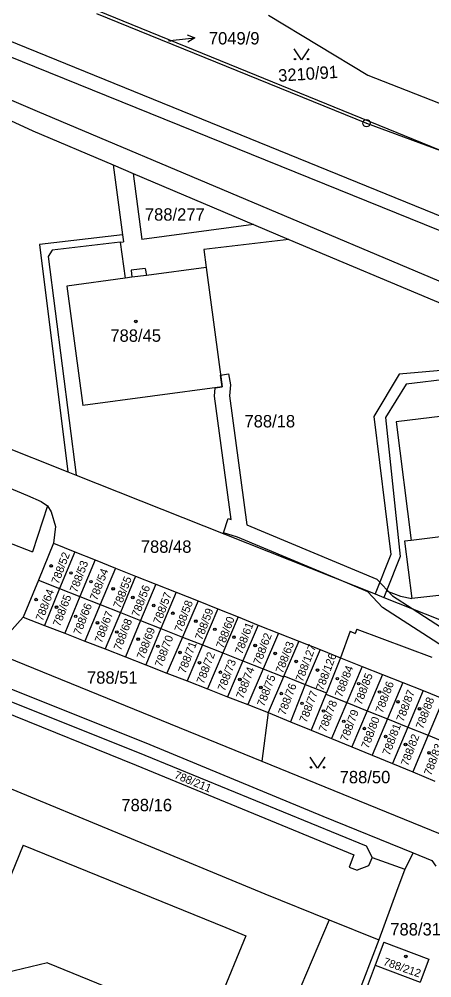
# Model space of a CAD drawing. Extents: x -593183 to -588034, y -1130415 to -1124994.
# Drawn here: x -591933.7 to -591877.1, y -1128398.9 to -1128267.2 of the extents above; entities that cross this region are included whole.
import ezdxf

# ---------------------------------------------------------------- set-up
doc = ezdxf.new("R2010")
doc.units = 0
for name, color, linetype in [('Vrstva 1', 7, 'Continuous'), ('Vrstva 16', 7, 'Continuous'), ('Vrstva 18', 7, 'Continuous'), ('Vrstva 19', 7, 'Continuous'), ('Vrstva 24', 7, 'Continuous'), ('Vrstva 25', 7, 'Continuous'), ('Vrstva 27', 7, 'Continuous'), ('Vrstva 4', 7, 'Continuous')]:
    doc.layers.add(name, color=color, linetype=linetype)

msp = doc.modelspace()

# ---------------------------------------------------------------- linework, layer by layer
at = {"layer": 'Vrstva 1'}
for p, q in [((-591960.97, -1128261.67), (-591931.65, -1128273.68)), ((-591955.86, -1128261.68), (-591814.3, -1128319.36)), ((-591875.91, -1128285.24), (-591925.43, -1128265.02)), ((-591923.14, -1128266.39), (-591886.05, -1128281.47)), ((-591899.53, -1128266.62), (-591885.86, -1128274.85)), ((-591946.82, -1128273.12), (-591931.29, -1128279.8)), ((-591931.65, -1128273.68), (-591845.27, -1128308.65)), ((-591885.86, -1128274.85), (-591849.68, -1128289.18)), ((-591947.36, -1128275.43), (-591931.88, -1128282.5)), ((-591931.29, -1128279.8), (-591692.48, -1128380.79)), ((-591886.05, -1128281.47), (-591875.91, -1128285.24)), ((-591931.88, -1128282.5), (-591920.82, -1128287.21)), ((-591920.82, -1128287.21), (-591918.08, -1128288.37)), ((-591920.82, -1128287.21), (-591919.56, -1128296.79)), ((-591918.08, -1128288.37), (-591901.57, -1128295.39)), ((-591901.57, -1128295.39), (-591896.73, -1128297.44)), ((-591919.56, -1128296.79), (-591919.43, -1128297.76)), ((-591896.73, -1128297.44), (-591908.41, -1128298.84)), ((-591896.73, -1128297.44), (-591875.33, -1128306.43)), ((-591919.87, -1128297.81), (-591919.43, -1128297.76)), ((-591919.87, -1128297.81), (-591919.2, -1128302.75)), ((-591908.41, -1128298.84), (-591908.06, -1128301.32)), ((-591916.44, -1128301.42), (-591918.36, -1128301.66)), ((-591916.44, -1128301.42), (-591916.27, -1128302.38)), ((-591908.06, -1128301.32), (-591916.27, -1128302.38)), ((-591908.06, -1128301.32), (-591905.88, -1128317.72)), ((-591918.25, -1128302.63), (-591919.2, -1128302.75)), ((-591918.36, -1128301.66), (-591918.25, -1128302.63)), ((-591919.2, -1128302.75), (-591927.21, -1128303.87)), ((-591927.21, -1128303.87), (-591925.02, -1128320.28)), ((-591905.88, -1128317.72), (-591925.02, -1128320.28)), ((-591873.96, -1128321.52), (-591881.99, -1128322.5)), ((-591881.99, -1128322.5), (-591879.92, -1128338.81)), ((-591938.97, -1128324.65), (-591927.04, -1128329.4)), ((-591927.04, -1128329.4), (-591925.93, -1128329.84)), ((-591925.93, -1128329.84), (-591884.86, -1128346.18)), ((-591935.41, -1128331.44), (-591932.59, -1128332.65)), ((-591932.59, -1128332.65), (-591930.7, -1128333.45)), ((-591930.7, -1128333.45), (-591929.87, -1128334.08)), ((-591929.87, -1128334.08), (-591929.34, -1128334.9)), ((-591929.34, -1128334.9), (-591928.74, -1128336.89)), ((-591928.74, -1128336.89), (-591929.02, -1128339.21)), ((-591866.81, -1128337.15), (-591879.92, -1128338.81)), ((-591929.02, -1128339.21), (-591931.1, -1128344.28)), ((-591929.02, -1128339.21), (-591926.1, -1128340.38)), ((-591926.1, -1128340.38), (-591928.18, -1128345.43)), ((-591926.1, -1128340.38), (-591923.31, -1128341.49)), ((-591923.31, -1128341.49), (-591925.4, -1128346.53)), ((-591923.31, -1128341.49), (-591920.53, -1128342.61)), ((-591920.53, -1128342.61), (-591922.62, -1128347.63)), ((-591920.53, -1128342.61), (-591917.75, -1128343.72)), ((-591931.1, -1128344.28), (-591933.18, -1128349.35)), ((-591931.1, -1128344.28), (-591928.18, -1128345.43)), ((-591917.75, -1128343.72), (-591919.84, -1128348.73)), ((-591917.75, -1128343.72), (-591914.96, -1128344.83)), ((-591914.96, -1128344.83), (-591917.06, -1128349.83)), ((-591914.96, -1128344.83), (-591912.18, -1128345.94)), ((-591928.18, -1128345.43), (-591930.26, -1128350.49)), ((-591928.18, -1128345.43), (-591925.4, -1128346.53)), ((-591912.18, -1128345.94), (-591914.28, -1128350.93)), ((-591912.18, -1128345.94), (-591909.18, -1128347.14)), ((-591884.86, -1128346.18), (-591883.66, -1128346.66)), ((-591925.4, -1128346.53), (-591927.48, -1128351.57)), ((-591925.4, -1128346.53), (-591922.62, -1128347.63)), ((-591909.18, -1128347.14), (-591911.32, -1128352.1)), ((-591909.18, -1128347.14), (-591906.47, -1128348.23)), ((-591883.66, -1128346.66), (-591865, -1128354.08)), ((-591922.62, -1128347.63), (-591924.71, -1128352.66)), ((-591922.62, -1128347.63), (-591919.84, -1128348.73)), ((-591919.84, -1128348.73), (-591921.93, -1128353.74)), ((-591919.84, -1128348.73), (-591917.06, -1128349.83)), ((-591906.47, -1128348.23), (-591908.57, -1128353.18)), ((-591906.47, -1128348.23), (-591903.69, -1128349.34)), ((-591933.18, -1128349.35), (-591935.12, -1128351.5)), ((-591933.18, -1128349.35), (-591930.26, -1128350.49)), ((-591917.06, -1128349.83), (-591919.15, -1128354.83)), ((-591917.06, -1128349.83), (-591914.28, -1128350.93)), ((-591903.69, -1128349.34), (-591905.8, -1128354.28)), ((-591903.69, -1128349.34), (-591900.91, -1128350.45)), ((-591930.26, -1128350.49), (-591927.48, -1128351.57)), ((-591914.28, -1128350.93), (-591916.37, -1128355.92)), ((-591914.28, -1128350.93), (-591911.32, -1128352.1)), ((-591900.91, -1128350.45), (-591903.02, -1128355.38)), ((-591900.91, -1128350.45), (-591898.12, -1128351.57)), ((-591888.31, -1128351.27), (-591889.61, -1128354.96)), ((-591888.31, -1128351.27), (-591887.61, -1128351.59)), ((-591887.4, -1128351.02), (-591887.61, -1128351.59)), ((-591887.4, -1128351.02), (-591877.07, -1128354.87)), ((-591927.48, -1128351.57), (-591924.71, -1128352.66)), ((-591924.71, -1128352.66), (-591921.93, -1128353.74)), ((-591911.32, -1128352.1), (-591913.45, -1128357.05)), ((-591911.32, -1128352.1), (-591908.57, -1128353.18)), ((-591898.12, -1128351.57), (-591900.23, -1128356.48)), ((-591898.12, -1128351.57), (-591895.34, -1128352.68)), ((-591895.34, -1128352.68), (-591897.39, -1128357.44)), ((-591895.34, -1128352.68), (-591892.43, -1128353.83)), ((-591937.65, -1128353.99), (-591900.44, -1128369.15)), ((-591921.93, -1128353.74), (-591919.15, -1128354.83)), ((-591908.57, -1128353.18), (-591910.67, -1128358.14)), ((-591908.57, -1128353.18), (-591905.8, -1128354.28)), ((-591892.43, -1128353.83), (-591894.48, -1128358.61)), ((-591892.43, -1128353.83), (-591889.61, -1128354.96)), ((-591919.15, -1128354.83), (-591916.37, -1128355.92)), ((-591905.8, -1128354.28), (-591907.9, -1128359.22)), ((-591905.8, -1128354.28), (-591903.02, -1128355.38)), ((-591903.02, -1128355.38), (-591905.12, -1128360.31)), ((-591903.02, -1128355.38), (-591900.23, -1128356.48)), ((-591889.61, -1128354.96), (-591891.57, -1128359.79)), ((-591889.61, -1128354.96), (-591886.66, -1128356.13)), ((-591916.37, -1128355.92), (-591913.45, -1128357.05)), ((-591900.23, -1128356.48), (-591902.34, -1128361.39)), ((-591900.23, -1128356.48), (-591897.45, -1128357.58)), ((-591886.66, -1128356.13), (-591888.76, -1128361.09)), ((-591886.66, -1128356.13), (-591883.87, -1128357.24)), ((-591939.08, -1128357.55), (-591915.81, -1128366.85)), ((-591913.45, -1128357.05), (-591910.67, -1128358.14)), ((-591897.45, -1128357.58), (-591899.56, -1128362.48)), ((-591897.39, -1128357.44), (-591897.45, -1128357.58)), ((-591897.39, -1128357.44), (-591894.48, -1128358.61)), ((-591883.87, -1128357.24), (-591885.96, -1128362.22)), ((-591883.87, -1128357.24), (-591881.07, -1128358.35)), ((-591910.67, -1128358.14), (-591907.9, -1128359.22)), ((-591907.9, -1128359.22), (-591905.12, -1128360.31)), ((-591894.48, -1128358.61), (-591896.49, -1128363.74)), ((-591894.48, -1128358.61), (-591891.57, -1128359.79)), ((-591881.07, -1128358.35), (-591883.17, -1128363.35)), ((-591881.07, -1128358.35), (-591878.28, -1128359.46)), ((-591905.12, -1128360.31), (-591902.34, -1128361.39)), ((-591891.63, -1128359.93), (-591893.65, -1128364.91)), ((-591891.57, -1128359.79), (-591891.63, -1128359.93)), ((-591891.63, -1128359.93), (-591888.76, -1128361.09)), ((-591878.28, -1128359.46), (-591880.38, -1128364.48)), ((-591878.28, -1128359.46), (-591875.49, -1128360.57)), ((-591875.49, -1128360.57), (-591877.59, -1128365.61)), ((-591902.34, -1128361.39), (-591899.56, -1128362.48)), ((-591888.76, -1128361.09), (-591890.86, -1128366.06)), ((-591888.76, -1128361.09), (-591885.96, -1128362.22)), ((-591936.21, -1128362.18), (-591917.66, -1128369.72)), ((-591899.56, -1128362.48), (-591900.44, -1128369.15)), ((-591899.56, -1128362.48), (-591896.49, -1128363.74)), ((-591885.96, -1128362.22), (-591888.06, -1128367.21)), ((-591885.96, -1128362.22), (-591883.17, -1128363.35)), ((-591883.17, -1128363.35), (-591885.27, -1128368.35)), ((-591883.17, -1128363.35), (-591880.38, -1128364.48)), ((-591896.49, -1128363.74), (-591893.65, -1128364.91)), ((-591880.38, -1128364.48), (-591882.48, -1128369.5)), ((-591880.38, -1128364.48), (-591877.59, -1128365.61)), ((-591893.65, -1128364.91), (-591890.86, -1128366.06)), ((-591877.59, -1128365.61), (-591879.69, -1128370.65)), ((-591877.59, -1128365.61), (-591874.62, -1128366.81)), ((-591915.81, -1128366.85), (-591892.05, -1128376.71)), ((-591890.86, -1128366.06), (-591888.06, -1128367.21)), ((-591888.06, -1128367.21), (-591885.27, -1128368.35)), ((-591947.64, -1128367.69), (-591900.03, -1128387.39)), ((-591885.27, -1128368.35), (-591882.48, -1128369.5)), ((-591917.66, -1128369.72), (-591887.81, -1128382.02)), ((-591900.44, -1128369.15), (-591875.93, -1128379.14)), ((-591882.48, -1128369.5), (-591879.69, -1128370.65)), ((-591879.69, -1128370.65), (-591876.67, -1128371.89)), ((-591892.05, -1128376.71), (-591879.67, -1128381.78)), ((-591933.2, -1128380.71), (-591935.39, -1128386.13)), ((-591933.2, -1128380.71), (-591905.39, -1128392.04)), ((-591879.67, -1128381.78), (-591880.8, -1128384.01)), ((-591879.67, -1128381.78), (-591877.1, -1128382.82)), ((-591887.81, -1128382.02), (-591888.45, -1128383.74)), ((-591885.27, -1128382.41), (-591885.8, -1128383.54)), ((-591885.27, -1128382.41), (-591880.8, -1128384.01)), ((-591877.1, -1128382.82), (-591876.53, -1128383.59)), ((-591888.45, -1128383.74), (-591887.36, -1128384.13)), ((-591885.8, -1128383.54), (-591887.36, -1128384.13)), ((-591880.8, -1128384.01), (-591881.93, -1128387.09)), ((-591900.03, -1128387.39), (-591891.2, -1128390.96)), ((-591881.93, -1128387.09), (-591884.38, -1128393.73)), ((-591891.2, -1128390.96), (-591899.06, -1128409.45)), ((-591891.2, -1128390.96), (-591884.38, -1128393.73)), ((-591905.39, -1128392.04), (-591902.61, -1128393.17)), ((-591902.61, -1128393.17), (-591907.82, -1128405.85)), ((-591884.38, -1128393.73), (-591892.67, -1128415.34)), ((-591883.67, -1128394.06), (-591884.86, -1128397.22)), ((-591883.67, -1128394.06), (-591877.48, -1128396.39)), ((-591929.86, -1128396.89), (-591949.87, -1128401.69)), ((-591929.86, -1128396.89), (-591907.82, -1128405.85)), ((-591884.86, -1128397.22), (-591885.97, -1128400.14)), ((-591884.86, -1128397.22), (-591878.67, -1128399.56)), ((-591877.48, -1128396.39), (-591878.67, -1128399.56))]:
    msp.add_line(p, q, dxfattribs=at)
at = {"layer": 'Vrstva 16'}
msp.add_line((-591913.26, -1128270.13), (-591912.62, -1128270.06), dxfattribs=at)
at = {"layer": 'Vrstva 24'}
for radius in [0.5, 0.0327]:
    msp.add_circle((-591886.05, -1128281.47), radius, dxfattribs=at)
at = {"layer": 'Vrstva 25'}
msp.add_line((-591912.62, -1128270.06), (-591909.64, -1128269.71), dxfattribs=at)
for points in [[(-591910.69, -1128269.33), (-591909.64, -1128269.71), (-591910.58, -1128270.33)], [(-591893.98, -1128271.26), (-591894.98, -1128272.76), (-591895.98, -1128271.26)], [(-591891.78, -1128368.61), (-591892.78, -1128370.11), (-591893.78, -1128368.61)]]:
    msp.add_lwpolyline(points, dxfattribs=at)
for centre, radius in [((-591895.88, -1128272.66), 0.1), ((-591894.08, -1128272.66), 0.1), ((-591917.73, -1128308.71), 0.175), ((-591917.73, -1128308.71), 0.15), ((-591929.34, -1128342.32), 0.175), ((-591929.34, -1128342.32), 0.15), ((-591926.63, -1128343.29), 0.175), ((-591926.63, -1128343.29), 0.15), ((-591923.88, -1128344.48), 0.175), ((-591923.88, -1128344.48), 0.15), ((-591920.83, -1128345.48), 0.175), ((-591920.83, -1128345.48), 0.15), ((-591931.42, -1128346.95), 0.175), ((-591931.42, -1128346.95), 0.15), ((-591918.15, -1128346.67), 0.175), ((-591918.15, -1128346.67), 0.15), ((-591928.6, -1128348), 0.175), ((-591928.6, -1128348), 0.15), ((-591915.27, -1128347.77), 0.175), ((-591915.27, -1128347.77), 0.15), ((-591912.65, -1128348.83), 0.175), ((-591912.65, -1128348.83), 0.15), ((-591925.98, -1128349.25), 0.175), ((-591925.98, -1128349.25), 0.15), ((-591923, -1128350.14), 0.175), ((-591923, -1128350.14), 0.15), ((-591909.49, -1128349.91), 0.175), ((-591909.49, -1128349.91), 0.15), ((-591920.34, -1128351.4), 0.175), ((-591920.34, -1128351.4), 0.15), ((-591906.87, -1128351.04), 0.175), ((-591906.87, -1128351.04), 0.15), ((-591917.41, -1128352.39), 0.175), ((-591917.41, -1128352.39), 0.15), ((-591904.25, -1128352.12), 0.175), ((-591904.25, -1128352.12), 0.15), ((-591914.69, -1128353.38), 0.175), ((-591914.69, -1128353.38), 0.15), ((-591911.66, -1128354.22), 0.175), ((-591911.66, -1128354.22), 0.15), ((-591901.35, -1128353.27), 0.175), ((-591901.35, -1128353.27), 0.15), ((-591908.99, -1128355.63), 0.175), ((-591898.6, -1128354.35), 0.175), ((-591898.6, -1128354.35), 0.15), ((-591895.72, -1128355.45), 0.175), ((-591895.72, -1128355.45), 0.15), ((-591908.99, -1128355.63), 0.15), ((-591906.12, -1128356.94), 0.175), ((-591892.78, -1128356.64), 0.175), ((-591892.78, -1128356.64), 0.15), ((-591906.12, -1128356.94), 0.15), ((-591903.45, -1128357.93), 0.175), ((-591903.45, -1128357.93), 0.15), ((-591890.06, -1128357.82), 0.175), ((-591890.06, -1128357.82), 0.15), ((-591900.57, -1128359.03), 0.175), ((-591900.57, -1128359.03), 0.15), ((-591887.14, -1128358.51), 0.175), ((-591887.14, -1128358.51), 0.15), ((-591897.75, -1128359.87), 0.175), ((-591897.75, -1128359.87), 0.15), ((-591884.26, -1128359.66), 0.175), ((-591884.26, -1128359.66), 0.15), ((-591894.91, -1128361.21), 0.175), ((-591894.91, -1128361.21), 0.15), ((-591881.74, -1128361), 0.175), ((-591881.74, -1128361), 0.15), ((-591878.77, -1128361.96), 0.175), ((-591878.77, -1128361.96), 0.15), ((-591891.95, -1128362.27), 0.175), ((-591891.95, -1128362.27), 0.15), ((-591889.18, -1128363.68), 0.175), ((-591889.18, -1128363.68), 0.15), ((-591886.35, -1128364.68), 0.175), ((-591886.35, -1128364.68), 0.15), ((-591883.43, -1128365.77), 0.175), ((-591883.43, -1128365.77), 0.15), ((-591880.71, -1128366.87), 0.175), ((-591880.71, -1128366.87), 0.15), ((-591877.47, -1128368.02), 0.175), ((-591877.47, -1128368.02), 0.15), ((-591893.68, -1128370.01), 0.1), ((-591891.88, -1128370.01), 0.1), ((-591880.66, -1128396), 0.175), ((-591880.66, -1128396), 0.15)]:
    msp.add_circle(centre, radius, dxfattribs=at)
at = {"layer": 'Vrstva 27'}
for p, q in [((-591906.1, -1128316.1), (-591904.99, -1128315.92)), ((-591904.99, -1128315.92), (-591904.75, -1128317.41)), ((-591905.88, -1128317.72), (-591906.1, -1128316.1)), ((-591906.92, -1128319.01), (-591906.83, -1128317.85)), ((-591906.83, -1128317.85), (-591905.88, -1128317.72)), ((-591904.75, -1128317.41), (-591904.87, -1128318.95)), ((-591904.64, -1128335.94), (-591906.92, -1128319.01)), ((-591904.87, -1128318.95), (-591902.48, -1128336.67)), ((-591905.67, -1128337.79), (-591905.06, -1128335.81)), ((-591905.06, -1128335.81), (-591904.64, -1128335.94)), ((-591902.48, -1128336.67), (-591884.66, -1128344.15)), ((-591903.76, -1128338.37), (-591905.67, -1128337.79)), ((-591889.84, -1128344.2), (-591903.76, -1128338.37)), ((-591885.87, -1128345.88), (-591889.84, -1128344.2)), ((-591884.66, -1128344.15), (-591882.51, -1128346.44)), ((-591883.84, -1128348.03), (-591885.87, -1128345.88)), ((-591882.51, -1128346.44), (-591879.81, -1128348.19)), ((-591873.32, -1128354.86), (-591883.84, -1128348.03)), ((-591879.81, -1128348.19), (-591872.17, -1128353.15))]:
    msp.add_line(p, q, dxfattribs=at)
at = {"layer": 'Vrstva 4'}
for p, q in [((-591918.08, -1128288.37), (-591916.88, -1128297.46)), ((-591901.57, -1128295.39), (-591916.88, -1128297.46)), ((-591919.56, -1128296.79), (-591930.93, -1128298.14)), ((-591930.93, -1128298.14), (-591927.04, -1128329.4)), ((-591919.87, -1128297.81), (-591929.23, -1128298.91)), ((-591929.23, -1128298.91), (-591929.74, -1128299.77)), ((-591929.74, -1128299.77), (-591925.93, -1128329.84)), ((-591916.27, -1128302.38), (-591918.25, -1128302.63)), ((-591874.27, -1128315.3), (-591881.58, -1128315.97)), ((-591881.58, -1128315.97), (-591885.05, -1128321.77)), ((-591874.53, -1128316.59), (-591880.62, -1128317.36)), ((-591880.62, -1128317.36), (-591883.43, -1128321.92)), ((-591885.05, -1128321.77), (-591882.7, -1128340.75)), ((-591883.43, -1128321.92), (-591881.43, -1128341.04)), ((-591929.87, -1128334.08), (-591931.89, -1128340.39)), ((-591935.43, -1128339.01), (-591931.89, -1128340.39)), ((-591879.92, -1128338.81), (-591880.83, -1128338.93)), ((-591880.83, -1128338.93), (-591879.84, -1128346.78)), ((-591882.7, -1128340.75), (-591884.86, -1128346.18)), ((-591881.43, -1128341.04), (-591883.29, -1128345.73)), ((-591883.29, -1128345.73), (-591883.66, -1128346.66)), ((-591883.29, -1128345.73), (-591881.37, -1128346.49)), ((-591865.94, -1128345.27), (-591879.84, -1128346.78)), ((-591881.37, -1128346.49), (-591879.84, -1128346.78)), ((-591936.98, -1128360.14), (-591916.47, -1128368.32)), ((-591916.47, -1128368.32), (-591886.09, -1128380.81)), ((-591886.09, -1128380.81), (-591885.27, -1128382.41))]:
    msp.add_line(p, q, dxfattribs=at)

# ---------------------------------------------------------------- texts
at = {"layer": 'Vrstva 16'}
msp.add_text('7049/9', height=1.7, dxfattribs=at).set_placement((-591907.7, -1128270.64))
at = {"layer": 'Vrstva 18'}
for s, height, rotation, p in [('7049/9', 0.1, 323.1301, (-591913.26, -1128270.13)), ('3210/91', 1.7, 3.7242, (-591898.13, -1128275.77)), ('788/211', 1.1, 337.7298, (-591912.54, -1128371.46))]:
    msp.add_text(s, height=height, rotation=rotation, dxfattribs=at).set_placement(p)
for s, p in [('788/277', (-591916.48, -1128294.86)), ('788/18', (-591902.81, -1128323.28)), ('788/48', (-591917.04, -1128340.52)), ('788/51', (-591924.43, -1128358.51)), ('788/50', (-591889.74, -1128372.2)), ('788/16', (-591919.71, -1128376.04)), ('788/31', (-591882.79, -1128393.12))]:
    msp.add_text(s, height=1.7, dxfattribs=at).set_placement(p)
at = {"layer": 'Vrstva 19'}
msp.add_text('788/45', height=1.7, dxfattribs=at).set_placement((-591921.22, -1128311.51))
for s, rotation, p in [('788/52', 69.2744, (-591928.34, -1128344.9)), ('788/53', 69.2744, (-591925.82, -1128346.06)), ('788/54', 69.2744, (-591923.06, -1128347.15)), ('788/55', 69.2744, (-591919.85, -1128348.24)), ('788/64', 69.2744, (-591930.5, -1128349.99)), ('788/56', 69.2744, (-591917.32, -1128349.43)), ('788/57', 69.2744, (-591914.36, -1128350.41)), ('788/65', 69.2744, (-591928.13, -1128350.74)), ('788/66', 69.2744, (-591925.31, -1128351.92)), ('788/58', 69.2744, (-591911.45, -1128351.52)), ('788/67', 69.2744, (-591922.4, -1128353.01)), ('788/59', 69.2744, (-591908.63, -1128352.61)), ('788/68', 69.2744, (-591919.79, -1128354.03)), ('788/60', 69.2744, (-591905.73, -1128353.75)), ('788/69', 69.2744, (-591916.63, -1128355.24)), ('788/61', 69.2744, (-591903.14, -1128354.55)), ('788/70', 69.2744, (-591914.14, -1128356.32)), ('788/62', 69.2744, (-591900.62, -1128356.01)), ('788/63', 69.2744, (-591897.56, -1128357.18)), ('788/71', 69.2744, (-591910.93, -1128357.19)), ('788/127', 69.2744, (-591894.82, -1128358.34)), ('788/72', 69.2744, (-591908.41, -1128358.62)), ('788/73', 69.2744, (-591905.52, -1128359.62)), ('788/126', 69.2744, (-591892.02, -1128359.56)), ('788/74', 69.2744, (-591902.99, -1128360.68)), ('788/84', 69.2744, (-591889.43, -1128360.49)), ('788/75', 69.2744, (-591900.1, -1128361.75)), ('788/85', 69.2744, (-591886.75, -1128361.52)), ('788/76', 69.2744, (-591897.22, -1128362.93)), ('788/86', 69.2744, (-591883.85, -1128362.65)), ('788/87', 69.2744, (-591880.99, -1128363.83)), ('788/77', 69.2744, (-591894.3, -1128363.96)), ('788/88', 69.2744, (-591878.31, -1128364.83)), ('788/78', 69.2744, (-591891.64, -1128365.26)), ('788/79', 69.2744, (-591888.68, -1128366.54)), ('788/80', 69.2744, (-591885.8, -1128367.52)), ('788/81', 69.2744, (-591882.9, -1128368.47)), ('788/82', 69.2744, (-591880.36, -1128369.91)), ('788/83', 69.2744, (-591877.19, -1128371.22)), ('788/212', 340.821, (-591883.85, -1128397.16))]:
    msp.add_text(s, height=1.1, rotation=rotation, dxfattribs=at).set_placement(p)

doc.saveas('drawing.dxf')
